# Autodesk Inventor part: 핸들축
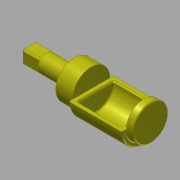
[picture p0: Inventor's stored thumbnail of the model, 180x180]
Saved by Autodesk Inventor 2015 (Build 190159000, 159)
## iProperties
Created: 2018-01
Part Number: 핸들축
Material: 강철, 연강
Document SubType Name: Modeling
Designer: mduedu
Density: 1 g/cm^3
Appearance: 노란색
Author: mduedu
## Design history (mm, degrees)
sketch "스케치1"
  geometry: L1 (0, 0)-(-38, 0); L2 (-38, 0)-(-38, -7.5); L3 (-38, -7.5)-(0, -7.5); L4 (0, -7.5)-(0, 0); L5 (-38, 0)-(-53, 0); L6 (-53, 0)-(-53, -16); L7 (-53, -16)-(-38, -16); L8 (-38, -16)-(-38, 0); L9 (-53, 0)-(-98, 0); L10 (-98, 0)-(-98, -19); L11 (-98, -19)-(-53, -19); L12 (-53, -19)-(-53, 0); L13 (-98, 0)-(-104, 0); L14 (-104, 0)-(-104, -15); L15 (-104, -15)-(-98, -15); L16 (-98, -15)-(-98, 0)
  constraints: 32 end point, 8 parallel, 4 horizontal, 4 perpendicular
  dimensions: "d0" = 6 distance of L14.end L15.end; "d2" = 30 diameter of L15 L13; "d3" = 32 diameter of L7 L5; "d4" = 15 distance of L6.end L7.end; "d5" = 45 distance of L10.end L11.end; "d6" = 38 diameter of L11 L9; "d7" = 38 distance of L2.end L3.end; "d8" = 15 diameter of L3 L1
revolve "회전1" sketch "스케치1" stored, may be unused: angle "d9" = 90 deg
sketch "스케치2"
  geometry: L1 (0, -7.5)-(0, 7.5) reference; L2 (0, 7.5)-(38, 7.5) reference; L3 (38, 7.5)-(38, 16) reference; L4 (38, 16)-(53, 16) reference; L5 (53, 16)-(53, 19) reference; L6 (53, 19)-(98, 19) reference; L7 (98, 19)-(98, 15) reference; L8 (98, 15)-(104, 15) reference; L9 (104, 15)-(104, -15) reference; L10 (104, -15)-(98, -15) reference; L11 (98, -15)-(98, -19) reference; L12 (98, -19)-(53, -19) reference; L13 (53, -19)-(53, -16) reference; L14 (53, -16)-(38, -16) reference; L15 (38, -16)-(38, -7.5) reference; L16 (38, -7.5)-(0, -7.5) reference; L17 (0, 0)-(104, 0); L18 (53, 19)-(53, 0); L19 (98, 19)-(98, 0); L20 (98, 0)-(53, 0); L21 (98, 19)-(53, 19)
  constraints: 10 end point, 3 perpendicular, 2 point on line, 1 midpoint, 1 parallel
extrude "돌출1" cut sketch "스케치2" stored distance "d10" = 10; taper "d11" = 0 deg
sketch "스케치3"
  geometry: L1 (45, 0)-(0, 0) reference; L2 (45, 4)-(45, 0) reference; L3 (45, 34)-(45, 4) reference; L4 (45, 38)-(45, 34) reference; L5 (0, 38)-(45, 38) reference; L6 (0, 35)-(0, 38) reference; L7 (0, 35)-(0, 3) reference; L8 (0, 0)-(0, 3) reference; L9 (0, 19)-(45, 19); L10 (4, 19)-(41, 19); L11 (41, 19)-(41, 34); L12 (41, 34)-(4, 34); L13 (4, 34)-(4, 19); 1 further point
  constraints: 10 end point, 2 midpoint, 2 parallel, 1 horizontal, 1 perpendicular, 1 point on line
  dimensions: "d12" = 4 distance between parallel lines of L3 L11; "d13" = 4 distance between parallel lines of L7 L13; "d14" = 4 distance between parallel lines of L12 L5
revolve "회전2" sketch "스케치3" stored, may be unused: angle "d15" = 90 deg
fillet "모깎기1" dims "d16" = 1
chamfer "모따기1" distance "d17" = 1; stored, may be unused: second distance "d18" = 2, angle "d19" = 45 deg
sketch "스케치4"
  geometry: L1 (-6, -6)-(-4.5, -6); L2 (6, -6)-(6, -4.5); L3 (6, 6)-(4.5, 6); L4 (-6, 6)-(-6, 4.5); L5 (-6, -6)-(6, 6); L6 (6, -6)-(-6, 6); L7 (-4.5, 6)-(-6, 6); L8 (-6, 4.5)-(-6, -4.5); L9 (-6, -4.5)-(-6, -6); L10 (-4.5, -6)-(4.5, -6); L11 (4.5, -6)-(6, -6); L12 (6, -4.5)-(6, 4.5); L13 (6, 4.5)-(6, 6); L14 (4.5, 6)-(-4.5, 6); C1 r 7.5 at (0, 0) reference; 2 further points
  constraints: 28 end point, 18 parallel, 9 perpendicular, 3 horizontal, 2 midpoint, 1 coincident, 11 other
  dimensions: "d20" = 12 distance of L4.start L3.start; "d21" = 12 distance of L3.start L2.start (= d20)
extrude "돌출2" cut sketch "스케치4" distance "d22" = 15; taper "d23" = 0 deg
chamfer "모따기2" distance "d24" = 1; stored, may be unused: second distance "d25" = 2, angle "d26" = 45 deg
sketch "스케치5"
  geometry: 2 further points
  constraints: 1 coincident
hole "구멍1" sketch "스케치5" at (5, 4.153) diameter "d27" = 2.459; stored, may be unused: countersink angle "d31" = 90 deg, drill point angle "d33" = 120 deg; dims "d28" = 6.9, "d29" = 4, "d30" = 2, "d32" = 8.4
node "솔리드1"
node "투영된 루프1"
node "절단 모서리 투영1"
